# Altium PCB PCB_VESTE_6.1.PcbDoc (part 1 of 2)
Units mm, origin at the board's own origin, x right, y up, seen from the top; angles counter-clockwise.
Board outline 60.48 x 91 mm, 4 copper layers (Top Copper (GND), Signal Layer 1 (PWR), Signal Layer 2 (GND), Bottom Copper(SIG)), stack 0.97 mm thick; 103 components, 68 nets, 385 pads, 720 vias.
Unrouted connection lines stored in the file: 5.
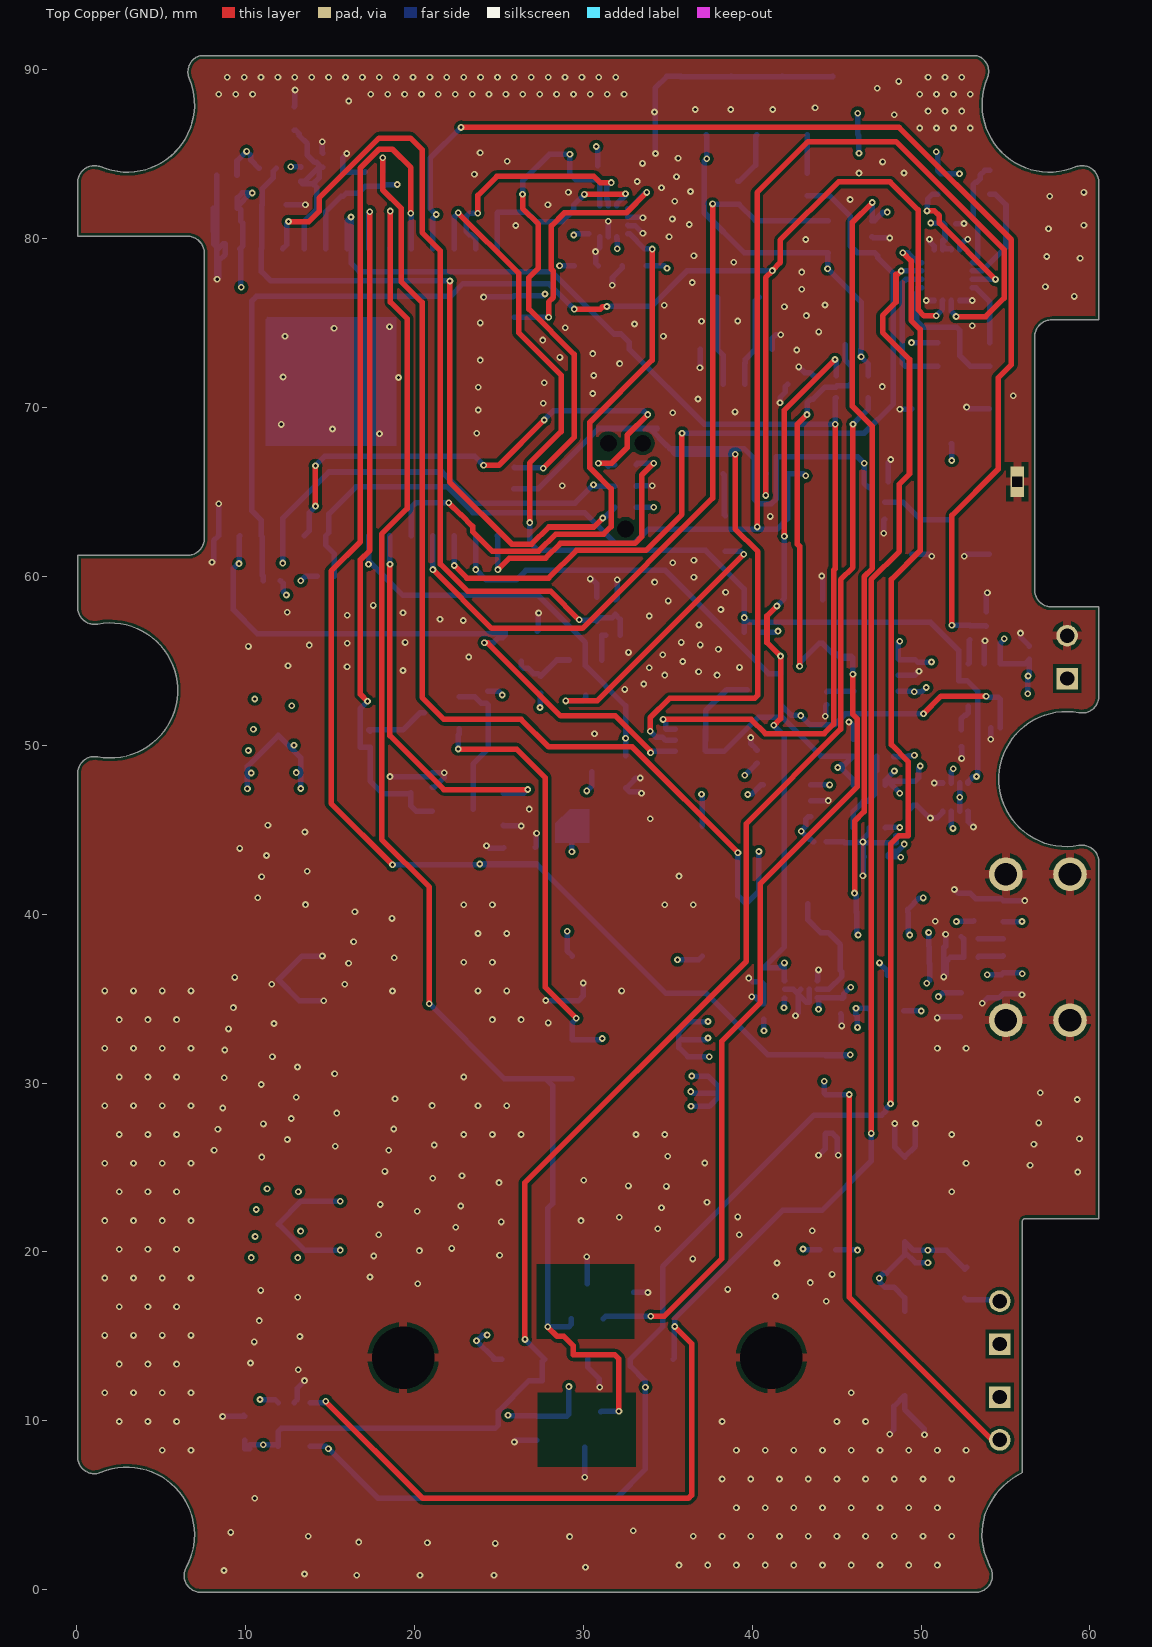
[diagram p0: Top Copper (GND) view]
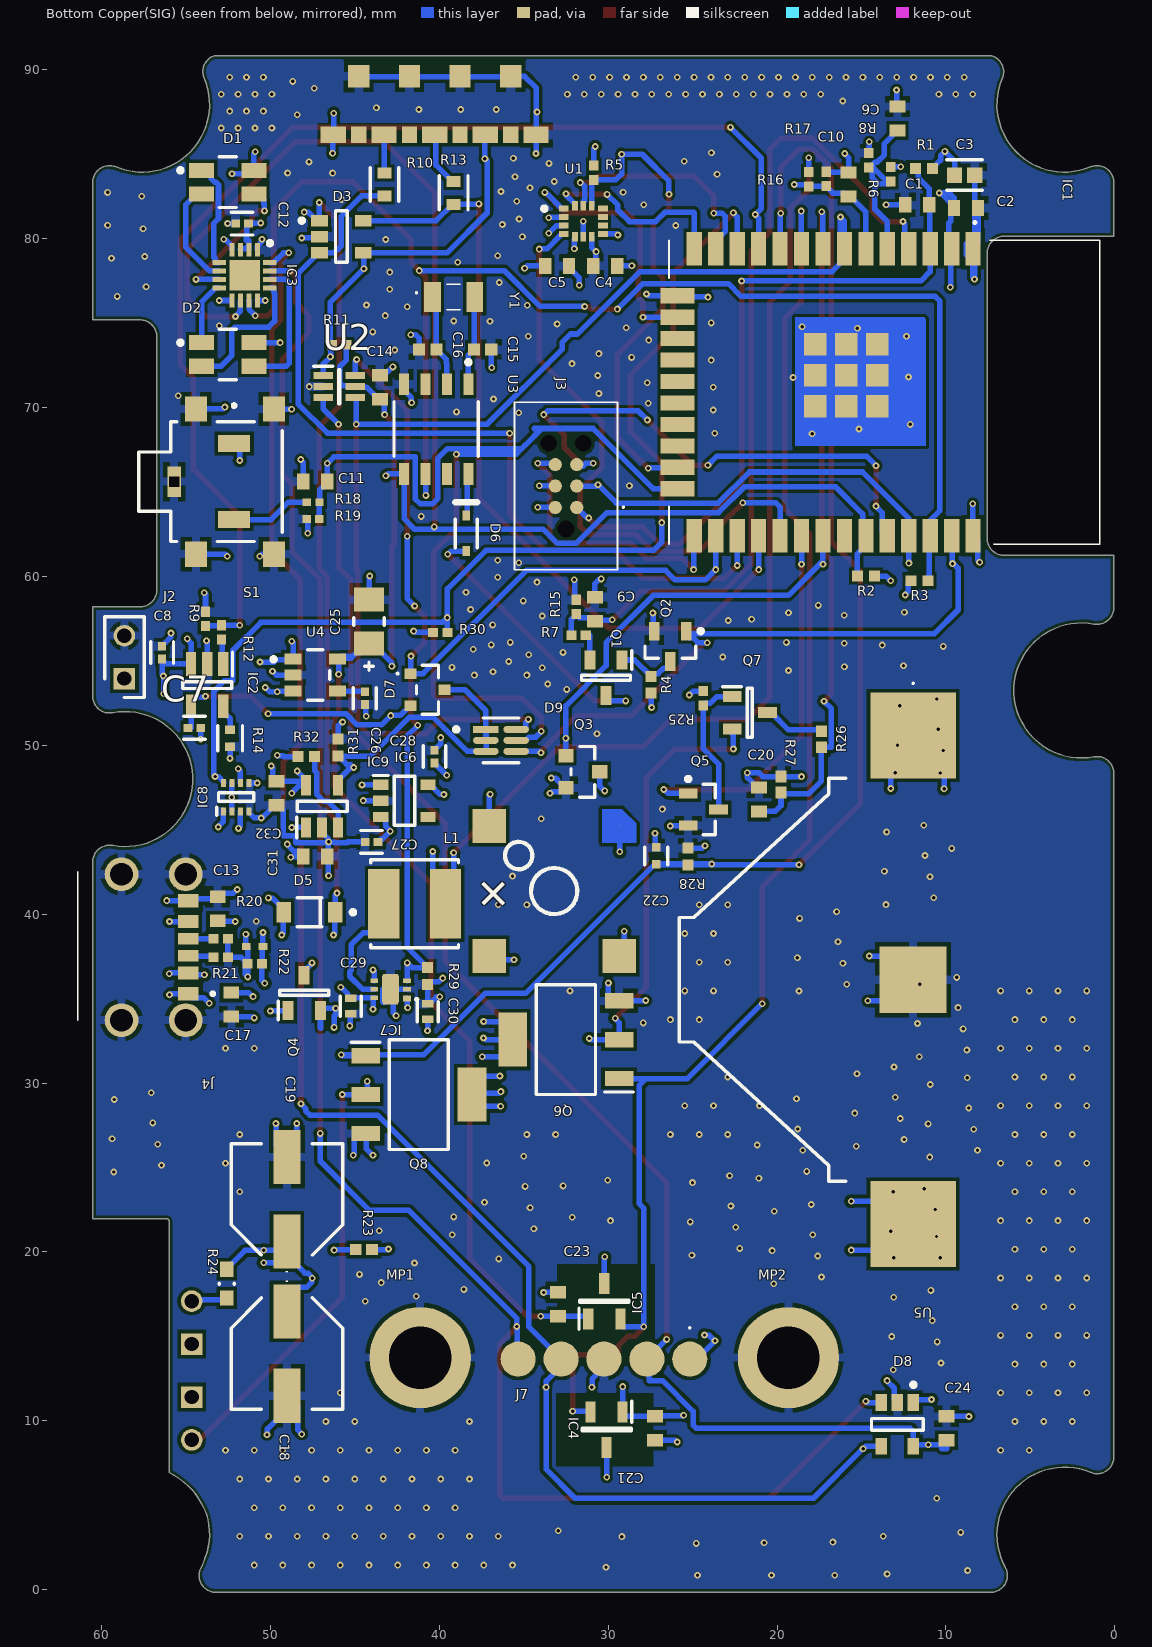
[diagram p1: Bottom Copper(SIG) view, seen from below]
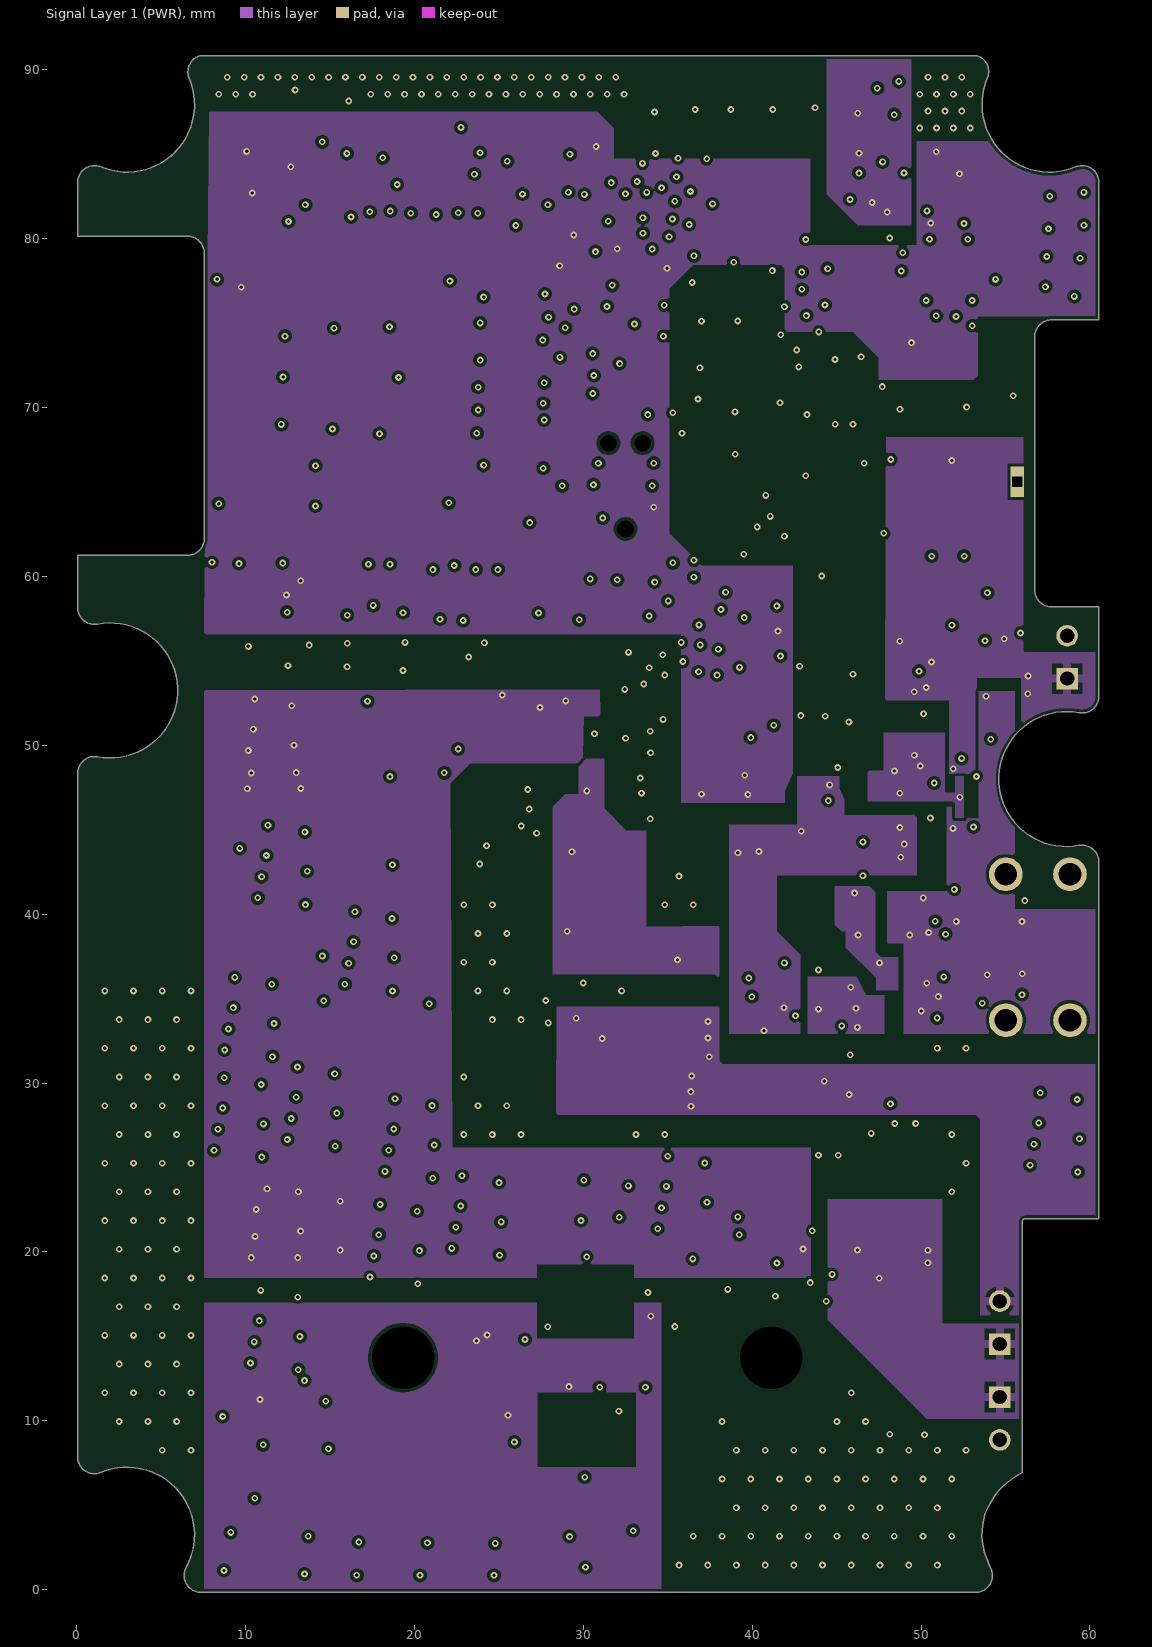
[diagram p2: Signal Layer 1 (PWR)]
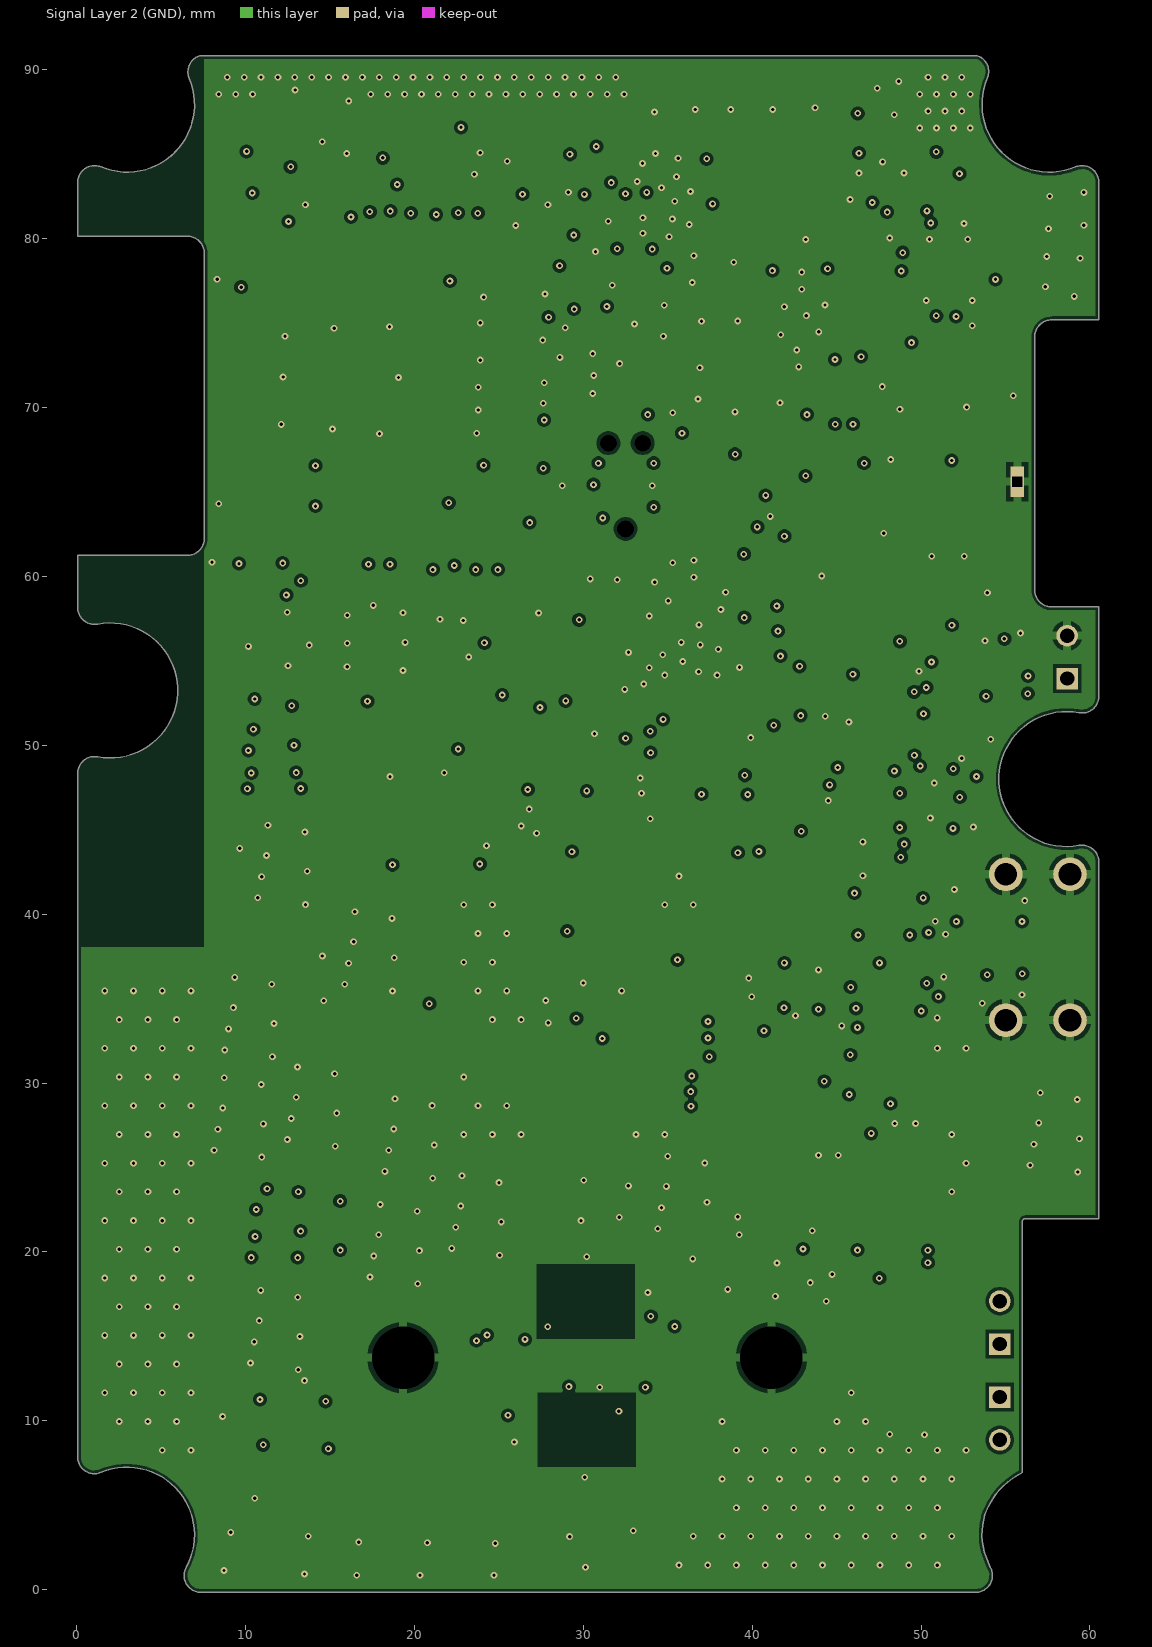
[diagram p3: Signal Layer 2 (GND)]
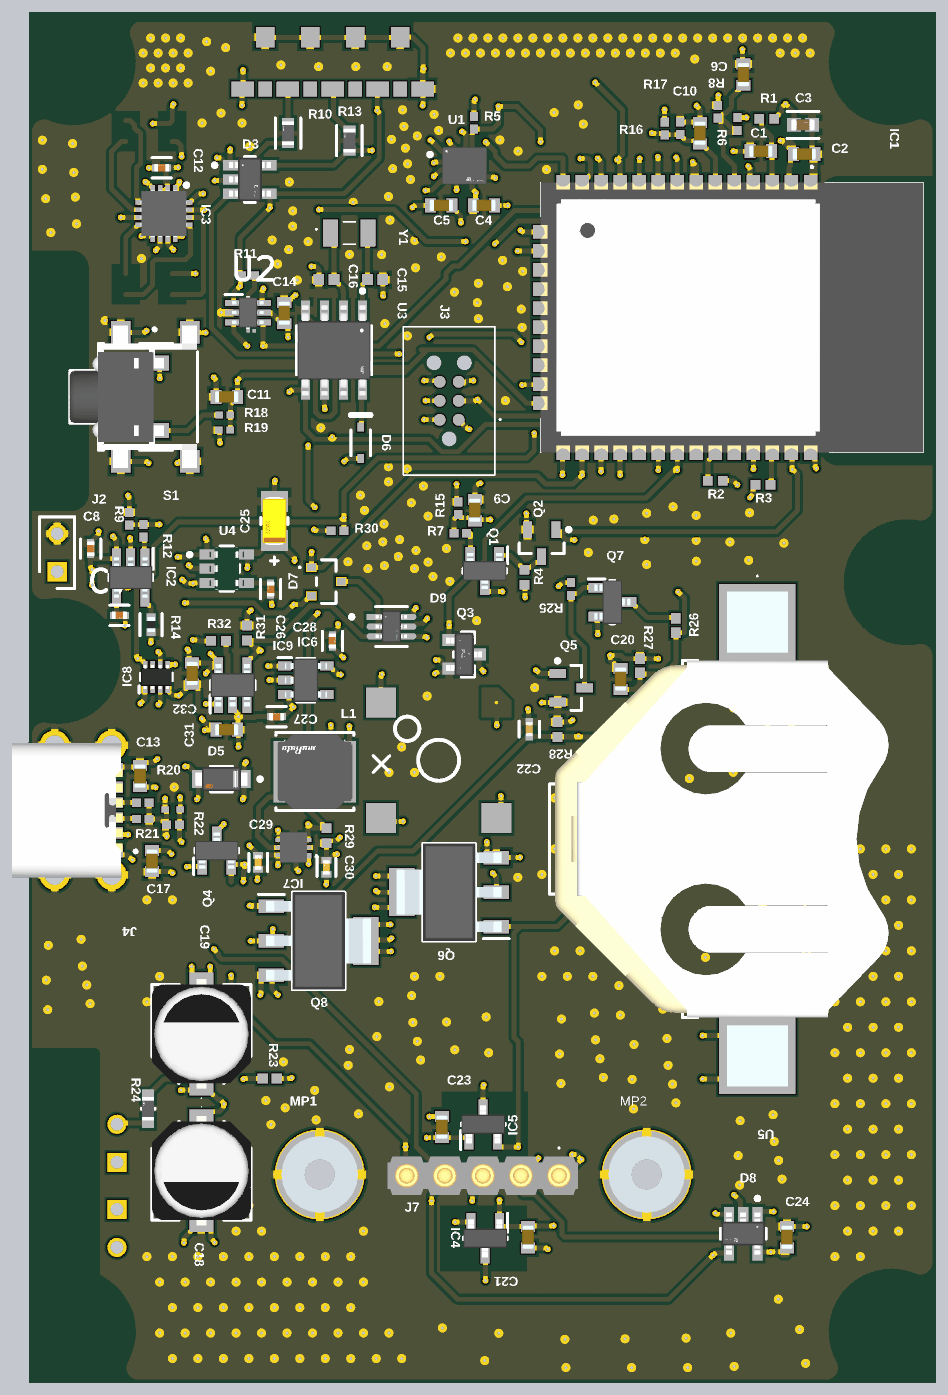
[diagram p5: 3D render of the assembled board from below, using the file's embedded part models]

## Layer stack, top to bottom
Top Mask: solder mask 0.015, Solder Resist, Dk 3.8
Top Copper (GND): signal copper 0.035
Dielectric 1: prepreg 0.2, 7628, Dk 4.6
Signal Layer 1 (PWR): signal copper 0.0175
Core: core 0.465, FR-4, Dk 4.5
Signal Layer 2 (GND): signal copper 0.0175
Dielectric 2: prepreg 0.2, 7628, Dk 4.6
Bottom Copper(SIG): signal copper 0.035
Bottom Mask: solder mask 0.015, Solder Resist, Dk 3.8

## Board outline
0.053,7.862 ccw(c1.053,7.862) 1.438,6.939 cw(c2.977,3.247) 6.482,1.319 ccw(c7.358,0.837) 7.358,-0.162 53.225,-0.162 ccw(c53.225,0.838) 54.102,1.319 cw(c58.745,3.625) 53.616,2.872 cw(c58.647,3.184) 53.767,4.447 cw(c58.841,2.431) 54.642,5.92 cw(c58.524,2.168) 55.996,6.939 55.993,9.925 55.993,14.87 cw(c55.995,14.866) 55.996,14.87 55.996,21.804 cw(c56.16,21.804) 56.159,21.968 60.53,21.968 60.53,43.083 ccw(c59.531,43.083) 59.346,44.066 cw(c58.607,47.997) 59.346,51.928 ccw(c59.53,52.911) 60.53,52.911 60.53,58.192 57.73,58.192 cw(c57.73,59.192) 56.73,59.192 56.73,74.192 cw(c57.73,74.192) 57.73,75.192 60.53,75.192 60.53,83.322 ccw(c59.531,83.322) 59.146,84.245 cw(c57.607,87.937) 53.923,89.496 ccw(c53.002,89.885) 53.308,90.838 7.3,90.838 ccw(c7.584,89.879) 6.663,89.49 cw(c2.977,87.936) 1.438,84.245 ccw(c1.053,83.322) 0.053,83.322 0.053,80.142 6.553,80.142 cw(c6.553,79.142) 7.553,79.142 7.553,62.242 cw(c6.554,62.241) 6.553,61.242 0.053,61.242 0.053,58.161 ccw(c1.053,58.161) 1.238,57.178 cw(c1.977,53.247) 1.238,49.316 ccw(c1.053,48.333) 0.053,48.333

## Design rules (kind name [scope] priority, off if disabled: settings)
BoardOutlineClearance [All] p1: gap=0.2 ignorepadtopadclearanceinfootprint=FALSE except(0.4: Arc-SplitBarrior Arc-SplitContinuation Track-SplitBarrior Track-SplitContinuation SMDPad-SplitBarrior SMDPad-SplitContinuation THPad-SplitBarrior THPad-SplitContinuation Via-SplitBarrior Via-SplitContinuation Fill-SplitBarrior Fill-SplitContinuation Poly-SplitBarrior Poly-SplitContinuation Region-SplitBarrior Region-SplitContinuation Text-SplitBarrior Text-SplitContinuation)
Clearance "Clearance Bottom Layer" [OnLayer('Bottom Layer')] p1: gap=0.203 ignorepadtopadclearanceinfootprint=TRUE except(0.254: Arc-Text Track-Text SMDPad-Text THPad-Text Via-Text Fill-Text Poly-Text Region-Text Text-Text)
Clearance "Clearance Top Layer" [OnLayer('Top Layer')] p2: gap=0.203 ignorepadtopadclearanceinfootprint=TRUE except(0.254: Arc-Text Track-Text SMDPad-Text THPad-Text Via-Text Fill-Text Poly-Text Region-Text Text-Text)
Clearance [All] p3: gap=0.2 ignorepadtopadclearanceinfootprint=FALSE except(0.089: Arc-Arc Arc-Track Arc-SMDPad Track-Track Track-SMDPad SMDPad-SMDPad; 0.127: Arc-Via Track-Via SMDPad-Via THPad-Via Via-Via; 0.254: Arc-Text Track-Text SMDPad-Text THPad-Text Via-Text Fill-Text Poly-Text Region-Text Text-Text)
HoleSize [All] p1: absolutevalues=TRUE maxlimit=6.3 minlimit=0.2 maxpercent=80.000 minpercent=20.000
MinimumAnnularRing [All] p1: minimumring=0.076
MinimumSolderMaskSliver [All] p1: minsoldermaskwidth=0.1
PolygonConnect PolygonConnect_1 [All] p1: thpad.connectstyle=Relief thpad.reliefconductorwidth=0.508 thpad.reliefentries=4 thpad.polygonreliefangle="90 Angle" thpad.airgapwidth=0.254 smdpad.connectstyle=Relief smdpad.reliefconductorwidth=0.508 smdpad.reliefentries=4 smdpad.polygonreliefangle="90 Angle" smdpad.airgapwidth=0.254 via.connectstyle=Direct via.reliefconductorwidth=0.508 via.reliefentries=4 via.polygonreliefangle="90 Angle" via.airgapwidth=0.254
RoomDefinition VESTE_V3.1_MCU [InComponentClass('VESTE_V3.1_MCU')] p1: confinementstyle=ConfineIn formatcopy=TRUE lockcomponents=FALSE outline -189.586,-112.446 -138.786,-112.446 -138.786,-87.046 -189.586,-87.046
RoutingCorners [All] p1: cornerstyle=Round minsetback=2.54 maxsetback=2.54
RoutingVias [All] p1: holewidth=0.2 width=0.4 viastyle="Through Hole" minholewidth=0.15 minwidth=0.3 maxholewidth=1 maxwidth=2
SilkToSilkClearance [All] p1: silktosilkclearance=0.1
SilkToSolderMaskClearance [IsPad] p1: minsilkscreentomaskgap=0.1 clearancetoexposedcopper=TRUE
SolderMaskExpansion [All] p1: expansion=0.102 istentingtop=FALSE
Width [All] p1: maxlimit=0.326 minlimit=0.217 preferedwidth=0.326 toplayer_minwidth=0.326 midlayer1_maxwidth=0.217 midlayer1_prefwidth=0.217 midlayer2_maxwidth=0.217 midlayer2_prefwidth=0.217 bottomlayer_minwidth=0.326 impedanceprofiledriven=TRUE impedanceprofileid={350D186C-2408-4C7B-B652-4617568C561D} impedanceprofilevalue=50.000000 minimp=50.000000 maximp=50.000000 favimp=50.000000
25 further rules are at their usual default settings.

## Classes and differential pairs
component class VESTE_V3.1_PSU: C7 C8 C13 C17 C18 C19 C25 C26 C27 C28 C29 C30 C31 C32 D5 D7 D9 IC2 IC6 IC7 IC8 IC9 J2 J4 L1 MP1 MP2 Q4 R9 R12 R14 R20 R21 R22 R23 R24 R29 R30 R31 R32 U4 U5
component class VESTE_V3.1_MCU: C1 C2 C3 C4 C5 C6 C9 C10 C11 C12 C14 C15 C16 C20 C21 C22 C23 C24 D1 D2 D3 D6 D8 IC1 IC3 IC4 IC5 J3 J7 Q1 Q2 Q3 Q5 Q6 Q7 Q8 R1 R2 R3 R4 R5 R6 R7 R8 R10 R11 R13 R15 R16 R17 R18 R19 R25 R26 R27 R28 S1 U1 U2 U3 Y1

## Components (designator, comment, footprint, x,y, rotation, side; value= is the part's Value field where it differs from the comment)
C1 "" CAPC1608X90N 11.705,82.004 r0 bottom
C2 "" CAPC1608X90N 8.808,81.813 r180 bottom
C3 "GRM188R61A226ME15D" FP-GRM188-0_2-IPC_C 8.89,83.762 r180 bottom
C4 "" CAPC1608X90N 30.18,78.39 r0 bottom
C5 "" CAPC1608X90N 33.025,78.39 r180 bottom
C6 "" CAPC1608X90N 12.867,87.115 r90 bottom
C7 "CL05A475KP5NRNC" FP-CL828-IPC_C 54.5,51.036 r180 bottom
C8 "CL05A475KP5NRNC" FP-CL828-IPC_C 56.417,55.486 r90 bottom
C9 "" CAPC1608X90N 30.787,58.056 r90 bottom
C10 "" CAPC1608X90N 15.765,83.209 r90 bottom
C11 "" CAPC1608X90N 47.34,65.614 r0 bottom
C12 "CL05A105KP5NNNC" FP-CL511-IPC_C 51.679,80.894 r0 bottom
C13 "" CAPC1608X90N 53.123,40.313 r90 bottom
C14 "" CAPC1608X90N 43.502,71.201 r90 bottom
C15 "CC0402JRNPO9BN100" CAPC1005X55X25ML05T05 37.435,73.44 r0 bottom
C16 "CC0402JRNPO9BN100" CAPC1005X55X25ML05T05 40.685,73.44 r180 bottom
C17 "" CAPC1608X90N 52.317,34.645 r270 bottom
C18 "EEEFT1A221AP" EEE1AA101SP 49.029,13.982 r270 bottom
C19 "EEEFT1A221AP" EEE1AA101SP 49.029,23.114 r90 bottom
C20 "" CAPC1608X90N 21.06,46.79 r90 bottom
C21 "" CAPC1608X90N 27.231,9.549 r270 bottom
C22 "CC0402KRX7R9BB103" FP-CC0402-MFG 27.154,43.449 r90 bottom value=10nF
C23 "" CAPC1608X90N 32.977,16.897 r90 bottom
C24 "" CAPC1608X90N 9.959,9.549 r90 bottom
C25 "TAJA225K016RNJ" FP-TAJA-MFG 44.162,57.33 r270 bottom
C26 "CL05B471KB5NNNC" FP-CL23-IPC_C 44.412,52.788 r270 bottom
C27 "CL05A105KP5NNNC" FP-CL511-IPC_C 44.014,44.277 r0 bottom
C28 "CL05A105KP5NNNC" FP-CL511-IPC_C 40.284,49.327 r90 bottom
C29 "CL05A106MP5NUNC" FP-CL05A106MP5NUNC-MFG 45.242,34.555 r270 bottom value=10uF
C30 "CL05A106MP5NUNC" FP-CL05A106MP5NUNC-MFG 40.687,34.227 r90 bottom value=10uF
C31 "" CAPC1608X90N 47.339,43.41 r0 bottom
C32 "" CAPC1608X90N 49.644,47.161 r270 bottom
D1 "150141M173100" WL-SFTW_3528_150141M173100 -1217.473,1353.343 r180 bottom locked
D2 "150141M173100" WL-SFTW_3528_150141M173100 -1217.473,1343.143 r180 bottom locked
D3 "SP0504BAHTG" FP-SP0504BAHTG-MFG 45.797,80.119 r180 bottom value=30pF
D5 "RB168MM100TR" FP-PMDU-MFG 47.692,40.113 r0 bottom
D6 "1N4148WS-7-F" DIOD-SOD323-2-A_V 38.404,62.547 r90 bottom
D7 "BAT54C" NXP-SOT23-3_V 40.698,53.288 r90 bottom
D8 "SP0504BAHTG" FP-SP0504BAHTG-MFG 12.879,9.784 r270 bottom value=30pF
D9 "SD103ATW-7-F" FP-SOT363-IPC_A 36.348,50.286 r180 bottom
IC1 "ESP32-WROOM-32__16MB_" ESP32WROOM3216MB 13.65,70.904 r270 bottom locked
IC2 "MCP73831-2ACI_OT" SOT95P270X145-5N 53.743,53.563 r270 bottom
IC3 "SC620ULTRT" QFN50P300X300X60-17N 51.527,77.837 r270 bottom
IC4 "TMAG5231A1CQDBZR" SOT95P237X112-3N 30.094,9.474 r270 bottom
IC5 "TMAG5231A1CQDBZR" SOT95P237X112-3N 30.231,17.076 r90 bottom
IC6 "XC6210B332MR-G" SOT95P280X130-5N 42.062,46.711 r180 bottom
IC7 "XC9142A50CER-G" XC9142A50CERG 42.887,35.555 r0 bottom
IC8 "TPS2116DRLR" SOTFL50P160X60-8N 52.027,46.927 r90 bottom
IC9 "AP2171WG-7" SOT95P282X130-5N 46.939,46.377 r90 bottom
J2 "3-644456-2" HDRV2W67P0X254_1X2_478X234X1029P 58.649,53.95 r270 bottom
J3 "TC2030-MCP-NL-10" TC2030MCPNL10 32.298,65.351 r90 bottom
J4 "TYPE-C-31-M-17" TYPEC31M17 57.367,38.04 r270 bottom locked
J7 "811-22-005-30-022101" 8112200530022101 30.25,13.65 r0 bottom
L1 "LQH5BPN4R7NT0L" FP-LQH5BPB_T0-MFG 41.462,40.613 r0 bottom
MP1 "9774035151R" 9774035151 41.135,13.735 r180 bottom
MP2 "9774035151R" 9774035151 19.325,13.735 r180 bottom
Q1 "DMP3125L-7" SOT96P240X110-3N 30.128,53.999 r270 bottom
Q2 "2N7002P,215" NXP-SOT23_L 26.323,55.862 r270 bottom
Q3 "DMN3730U-7" FP-SOT23-MFG 31.503,48.428 r180 bottom
Q4 "DMP3125L-7" SOT96P240X110-3N 48.006,35.343 r90 bottom
Q5 "2N7002P,215" NXP-SOT23_L 24.367,46.202 r180 bottom
Q6 "NDT3055L" SOT230P700X180-4N 32.503,32.566 r0 bottom
Q7 "DMP3125L-7" SOT96P240X110-3N 21.615,51.926 r180 bottom
Q8 "NDT3055L" SOT230P700X180-4N 41.211,29.316 r180 bottom
R1 "ERJ-2GEJ103X" RESC1005X40X25ML05T05 11.303,84.162 r180 bottom
R2 "ERJ-2GEJ103X" RESC1005X40X25ML05T05 14.74,60.018 r0 bottom
R3 "ERJ-2GEJ103X" RESC1005X40X25ML05T05 11.557,59.743 r180 bottom
R4 "ERJ-2GEJ103X" RESC1005X40X25ML05T05 27.47,53.586 r90 bottom
R5 "RC0402FR-07100KL" RESC1005X40X25NL05T10 30.848,83.902 r90 bottom
R6 "RC0402FR-07100KL" RESC1005X40X25NL05T10 13.267,83.812 r90 bottom
R7 "RC0402FR-07100KL" RESC1005X40X25NL05T10 31.751,56.514 r180 bottom
R8 "RC0402FR-07100KL" RESC1005X40X25NL05T10 14.576,84.643 r270 bottom
R9 "RC0402FR-079K1L" RESC1005X40X25NL05T10 53.845,57.48 r90 bottom
R10 "RC0603FR-071KL" FP-RC0603-0_55-IPC_C 43.249,83.209 r90 bottom
R11 "RC0402FR-07100KL" RESC1005X40X25NL05T10 45.923,73.715 r0 bottom
R12 "RC0402FR-074K7L" RESC1005X40X25NL05T10 52.895,56.683 r270 bottom
R13 "RC0603FR-071KL" FP-RC0603-0_55-IPC_C 39.154,82.709 r90 bottom
R14 "RC0402FR-072KL" FP-RC_L0402-MFG 52.39,50.411 r270 bottom value=2kΩ
R15 "RC0402FR-07100KL" RESC1005X40X25NL05T10 31.89,58.189 r270 bottom
R16 "RC0402FR-07100KL" RESC1005X40X25NL05T10 18.122,83.523 r90 bottom
R17 "RC0402FR-07100KL" RESC1005X40X25NL05T10 17.08,83.537 r270 bottom
R18 "RC0402FR-0730KL" RESC1005X40X25LL05T10 47.469,64.397 r180 bottom
R19 "RC0402FR-07110KL" RESC1005X40X25LL05T10 47.484,63.397 r180 bottom
R20 "RC0402FR-075K1L" RESC1005X40X25NL05T10 52.945,38.54 r0 bottom
R21 "RC0402FR-075K1L" RESC1005X40X25NL05T10 52.945,37.452 r0 bottom
R22 "RC0402FR-07100KL" RESC1005X40X25NL05T10 50.928,37.069 r180 bottom
R23 "RC0402FR-0756KL" RESC1005X40X25ML05T10 44.47,20.139 r180 bottom
R24 "RC0603FR-0747KL" FP-RC0603FR-0747KL-MFG 52.582,18.119 r90 bottom
R25 "RC0402FR-07100KL" RESC1005X40X25NL05T10 24.367,52.788 r90 bottom
R26 "RC0402FR-0756KL" RESC1005X40X25ML05T10 17.377,50.354 r270 bottom
R27 "RC0402FR-0768KL" RESC1005X40X25ML05T10 19.766,47.669 r90 bottom
R28 "ERJ-2GEJ103X" RESC1005X40X25ML05T05 25.277,43.423 r270 bottom
R29 "ERJ-2GEJ103X" RESC1005X40X25ML05T05 40.687,36.337 r270 bottom
R30 "RC0402FR-07100KL" RESC1005X40X25NL05T10 39.945,56.683 r180 bottom
R31 "ERJ-2GEJ103X" RESC1005X40X25ML05T05 45.989,49.861 r90 bottom
R32 "ERJ-2GEJ103X" RESC1005X40X25ML05T05 47.881,49.336 r0 bottom
S1 "TL3336AF160Q" TL3336AF160Q 52.6,65.614 r90 bottom
U1 "LSM6DS3TR" FP-LGA-14-DM00249496-MFG 31.475,81.031 r180 bottom
U2 "SN74AUP2G04DCKR" SOT65P210X110-6N 45.923,71.24 r180 bottom
U3 "PCF8563T/5,518" FP-SOT96-1-MFG 40.185,68.727 r270 bottom
U4 "MIC5205-3.3YM5-TR" FP-M5-MFG 47.34,54.156 r180 bottom
U5 "3024-2" 30242 11.941,36.116 r270 bottom
Y1 "Q13FC1350000400" Q13FC1350000400 39.154,76.542 r180 bottom

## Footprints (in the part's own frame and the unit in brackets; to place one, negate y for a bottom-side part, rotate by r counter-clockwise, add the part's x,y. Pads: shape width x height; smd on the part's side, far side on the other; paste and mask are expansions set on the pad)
30242 [mm]
  rect 5.08x5.08 smd: 1(-14.465,0) 2(14.465,0)
  rect 3.96x3.96 smd: 3(0,0)
  silkscreen extent -17.6,-13.85 11.93,0.05, body extent -17.01,-13.49 17.01,8.76, height 0.1
9774035151 [mm] "SMT Steel Spacer with internal Thread M2.5, height 3.5mm"
  round 6 / inner round 0 / far side round 0 hole 3.7 unplated: 1(0,0)
  body extent -2.55,-2.55 2.55,2.55, height 3.5
8112200530022101 [mm]
  round 2.08 smd: 1(-5.08,0) 2(-2.54,0) 3(0,0) 4(2.54,0) 5(5.08,0)
  silkscreen extent -5.13,-1.9 -5.03,-1.8, body extent -6.35,-1.27 6.35,1.27, height 3.49
CAPC1005X55X25ML05T05 [mm] "Chip Capacitor, 2-Leads, Body 1.00x0.50mm, IPC Low Density"
  rect 0.72x0.72 smd: 1(-0.51,0) 2(0.51,0)
  body extent -0.53,-0.28 0.53,0.27, height 0.55
CAPC1608X90N [mm]
  rect 0.73x0.94 smd: 1(-0.71,0) 2(0.71,0)
  body extent -0.8,-0.4 0.8,0.4, height 0.9
DIOD-SOD323-2-A_V [mm] "SOD-323, 2-Leads, Body 1.7x1.3mm"
  rect 0.59x0.45 smd: 1(-1.055,0) 2(1.055,0)
  silkscreen extent -0.85,-0.65 1.85,0.65, body extent -0.85,-0.65 0.85,0.65, height 1.2
EEE1AA101SP [mm]
  rect 3.2x1.6 smd: 1(-2.5,0) 2(2.5,0)
  silkscreen extent -4.88,-3.3 3.3,3.3, body extent -3.65,-3.3 3.65,3.3, height 5.8
ESP32WROOM3216MB [mm]
  rect 2x0.9 smd: 1(-8.5,5.26) 2(-8.5,3.99) 3(-8.5,2.72) 4(-8.5,1.45) 5(-8.5,0.18) 6(-8.5,-1.09) 7(-8.5,-2.36) 8(-8.5,-3.63) 9(-8.5,-4.9) 10(-8.5,-6.17) 11(-8.5,-7.44) 12(-8.5,-8.71) 13(-8.5,-9.98) 14(-8.5,-11.25) 25(8.5,-11.25) 26(8.5,-9.98) 27(8.5,-8.71) 28(8.5,-7.44) 29(8.5,-6.17) 30(8.5,-4.9) 31(8.5,-3.63) 32(8.5,-2.36) 33(8.5,-1.09) 34(8.5,0.18) 35(8.5,1.45) 36(8.5,2.72) 37(8.5,3.99) 38(8.5,5.26)
  rect 0.9x2 smd: 15(-5.715,-12.25) 16(-4.445,-12.25) 17(-3.175,-12.25) 18(-1.905,-12.25) 19(-0.635,-12.25) 20(0.635,-12.25) 21(1.905,-12.25) 22(3.175,-12.25) 23(4.445,-12.25) 24(5.715,-12.25)
  rect 1.33x1.33 smd: 39(-2.835,-0.405) 40(-1,-0.405) 41(0.835,-0.405) 42(-2.835,-2.24) 43(-1,-2.24) 44(0.835,-2.24) 45(-2.835,-4.075) 46(-1,-4.075) 47(0.835,-4.075)
  silkscreen extent -10.1,-12.75 9,12.75, body extent -9,-12.75 9,12.75, height 3.1
FP-CC0402-MFG [mm]
  rect 0.5x0.5 smd paste+0 mask+0: 1(-0.5,0) 2(0.5,0)
  silkscreen extent -0.53,-0.68 0.52,0.67, body extent -0.5,-0.25 0.5,0.25, height 0.55
FP-CL05A106MP5NUNC-MFG [mm]
  rect 0.45x0.675 smd paste+0 mask+0: 1(-0.463,0) 2(0.462,0)
  silkscreen extent -0.6,-0.63 0.6,0.63, body extent -0.5,-0.25 0.5,0.25, height 0.7
FP-CL23-IPC_C [mm]
  rect 0.515x0.472 smd paste+0 mask+0: 1(-0.379,0) 2(0.379,0)
  silkscreen extent -0.64,-0.67 0.64,0.68, body extent -0.5,-0.25 0.5,0.25, height 0.55
FP-CL511-IPC_C [mm]
  rect 0.515x0.472 smd paste+0 mask+0: 1(-0.379,0) 2(0.379,0)
  silkscreen extent -0.64,-0.68 0.64,0.67, body extent -0.5,-0.25 0.5,0.25, height 0.55
FP-CL828-IPC_C [mm]
  rect 0.515x0.472 smd paste+0 mask+0: 1(-0.379,0) 2(0.379,0)
  silkscreen extent -0.64,-0.67 0.64,0.67, body extent -0.5,-0.25 0.5,0.25, height 0.55
FP-GRM188-0_2-IPC_C [mm]
  rect 0.905x0.906 smd paste+0 mask+0: 1(-0.601,0) 2(0.601,0)
  silkscreen extent -1.05,-0.9 1.05,0.9, body extent -0.8,-0.4 0.8,0.4, height 1
FP-LGA-14-DM00249496-MFG [mm]
  rect 0.575x0.35 smd paste+0 mask+0: 1(-1.162,0.75) 2(-1.162,0.25) 3(-1.162,-0.25) 4(-1.162,-0.75) 8(1.163,-0.75) 9(1.163,-0.25) 10(1.163,0.25) 11(1.163,0.75)
  rect 0.35x0.575 smd paste+0 mask+0: 5(-0.5,-0.912) 6(0,-0.912) 7(0.5,-0.912) 12(0.5,0.913) 13(0,0.913) 14(-0.5,0.913)
  silkscreen extent -2.43,0.63 -2.18,0.87, body extent -1.5,-1.25 1.5,1.25, height 0.86
FP-LQH5BPB_T0-MFG [mm]
  rect 1.85x4.1 smd paste+0 mask+0: 1(-1.825,0) 2(1.825,0)
  silkscreen extent -2.6,-2.6 2.6,2.6, body extent -2.5,-2.5 2.5,2.5, height 2.2
FP-M5-MFG [mm]
  rect 1x0.66 smd paste+0 mask+0: 1(-1.315,0.95) 2(-1.315,0) 3(-1.315,-0.95) 4(1.315,-0.95) 5(1.315,0.95)
  silkscreen extent -2.6,-1.5 0.85,1.5, body extent -1.4,-1.46 1.4,1.46, height 1.3
FP-PMDU-MFG [mm]
  rect 0.85x1.2 smd paste+0 mask+0: 1(-1.525,0) 2(1.525,0)
  silkscreen extent -2.7,-0.85 0.73,0.85, body extent -1.75,-0.8 1.75,0.8, height 0.9
FP-RC0603-0_55-IPC_C [mm]
  rect 0.659x0.812 smd paste+0 mask+0: 1(-0.677,0) 2(0.677,0)
  silkscreen extent -1.01,-0.85 1.01,0.85, body extent -0.8,-0.4 0.8,0.4, height 0.55
FP-RC0603FR-0747KL-MFG [mm]
  rect 0.9x0.8 smd paste+0 mask+0: 1(-0.85,0) 2(0.85,0)
  silkscreen extent -0.02,-0.45 0.02,0.45, body extent -0.8,-0.4 0.8,0.4, height 0.55
FP-RC_L0402-MFG [mm]
  rect 0.5x0.6 smd paste+0 mask+0: 1(-0.5,0) 2(0.5,0)
  silkscreen extent -0.74,-0.74 0.74,0.74, body extent -0.5,-0.25 0.5,0.25, height 0.4
FP-SOT23-MFG [mm]
  rect 0.9x0.8 smd paste+0 mask+0: 1(-1,0.95) 2(-1,-0.95) 3(1,0)
  silkscreen extent -0.7,-1.5 0.7,1.5, body extent -1.2,-1.45 1.2,1.45, height 1.1
FP-SOT96-1-MFG [mm]
  rect 1.3x0.6 smd paste+0 mask+0: 1(-2.65,1.905) 2(-2.65,0.635) 3(-2.65,-0.635) 4(-2.65,-1.905) 5(2.65,-1.905) 6(2.65,-0.635) 7(2.65,0.635) 8(2.65,1.905)
  silkscreen extent -4.07,-2.5 1.62,2.5, body extent -2.99,-2.45 3.01,2.45, height 1.75
FP-SOT363-IPC_A [mm]
  rect 1.51x0.412 smd paste+0 mask+0: 1(-0.901,0.65)
  rrect100% 1.51x0.412 smd paste+0 mask+0: 2(-0.901,0) 3(-0.901,-0.65) 4(0.901,-0.65) 5(0.901,0) 6(0.901,0.65)
  silkscreen extent -2.78,-1.32 1.05,1.32, body extent -1.05,-1.07 1.05,1.07, height 1.1
FP-SP0504BAHTG-MFG [mm]
  rect 0.99x0.69 smd paste+0 mask+0: 1(-1.295,0.95) 2(-1.295,0) 3(-1.295,-0.95) 4(1.295,-0.95) 5(1.295,0.95)
  silkscreen extent -2.48,-1.52 0.35,1.53, body extent -1.4,-1.45 1.4,1.45, height 1.45
FP-TAJA-MFG [mm]
  rect 1.4x1.8 smd paste+0 mask+0: 1(-1.3,0) 2(1.3,0)
  silkscreen extent -0.23,-0.9 2.9,0.9, body extent -1.6,-0.8 1.6,0.8, height 1.8
HDRV2W67P0X254_1X2_478X234X1029P [mm]
  rect 1.275x1.275 hole 0.85: 1(0,0)
  round 1.275 hole 0.85: 2(-2.54,0)
  silkscreen extent -3.66,-1.17 1.12,1.17
NXP-SOT23-3_V [mm] "SOT23, 3-Leads, Body 1.3x2.9mm, Pitch 0.95mm"
  rect 0.6x0.7 smd paste-0.05: 1(0.95,1) 2(-0.95,1) 3(0,-1)
  silkscreen extent -1.45,-0.65 1.45,1.79, body extent -1.45,-0.65 1.45,0.65, height 1.1
NXP-SOT23_L [mm] "SOT23, 3-Leads, Body 3x1.4mm, Pitch 0.95mm, IPC High Density"
  rect 1.1x0.6 smd: 1(-0.9,0.95) 2(-0.9,-0.95) 3(0.9,0)
  silkscreen extent -1.02,-1.5 0.7,1.92, body extent -0.7,-1.5 0.7,1.5, height 1.1
Q13FC1350000400 [mm]
  rect 1x1.8 smd: 1(-1.25,0) 2(1.25,0)
  silkscreen extent -2.25,-0.75 0.4,0.75
QFN50P300X300X60-17N [mm]
  rect 0.8x0.3 smd: 1(-1.5,0.75) 2(-1.5,0.25) 3(-1.5,-0.25) 4(-1.5,-0.75) 9(1.5,-0.75) 10(1.5,-0.25) 11(1.5,0.25) 12(1.5,0.75)
  rect 0.3x0.8 smd: 5(-0.75,-1.5) 6(-0.25,-1.5) 7(0.25,-1.5) 8(0.75,-1.5) 13(0.75,1.5) 14(0.25,1.5) 15(-0.25,1.5) 16(-0.75,1.5)
  rect 1.8x1.8 smd: 17(0,0)
  silkscreen extent -2.02,1.37 -1.78,1.62, body extent -1.55,-1.55 1.55,1.55, height 0.6
RESC1005X40X25LL05T10 [mm] "Chip Resistor, 2-Leads, Body 1.00x0.50mm, IPC High Density"
  rect 0.5x0.45 smd: 1(-0.375,0) 2(0.375,0)
  body extent -0.53,-0.27 0.53,0.28, height 0.4
RESC1005X40X25ML05T05 [mm] "Chip Resistor, 2-Leads, Body 1.00x0.50mm, IPC Low Density"
  rect 0.65x0.65 smd: 1(-0.5,0) 2(0.5,0)
  body extent -0.53,-0.27 0.53,0.28, height 0.4
RESC1005X40X25ML05T10 [mm] "Chip Resistor, 2-Leads, Body 1.00x0.50mm, IPC Low Density"
  rect 0.7x0.65 smd: 1(-0.475,0) 2(0.475,0)
  body extent -0.53,-0.27 0.53,0.28, height 0.4
RESC1005X40X25NL05T10 [mm] "Chip Resistor, 2-Leads, Body 1.00x0.50mm, IPC Medium Density"
  rect 0.6x0.55 smd: 1(-0.425,0) 2(0.425,0)
  body extent -0.53,-0.27 0.53,0.28, height 0.4
SOT65P210X110-6N [mm]
  rect 1.15x0.4 smd: 1(-0.95,0.65) 2(-0.95,0) 3(-0.95,-0.65) 4(0.95,-0.65) 5(0.95,0) 6(0.95,0.65)
  silkscreen extent -1.53,-1.01 0.03,1.2, body extent -1.05,-1.01 1.05,1.01, height 1.1
SOT95P237X112-3N [mm]
  rect 1.25x0.6 smd: 1(-1.05,0.95) 2(-1.05,-0.95) 3(1.05,0)
  silkscreen extent -1.67,-1.46 0.08,1.5, body extent -1.27,-1.46 1.27,1.46, height 1
SOT95P270X145-5N [mm]
  rect 1.4x0.6 smd: 1(-1.25,0.95) 2(-1.25,0) 3(-1.25,-0.95) 4(1.25,-0.95) 5(1.25,0.95)
  silkscreen extent -1.95,-1.45 0.2,1.5, body extent -1.35,-1.45 1.35,1.45, height 1.45
SOT95P280X130-5N [mm]
  rect 0.9x0.6 smd: 1(-1.4,0.95) 2(-1.4,0) 3(-1.4,-0.95) 4(1.4,-0.95) 5(1.4,0.95)
  silkscreen extent -1.85,-1.45 0.6,1.5, body extent -1.4,-1.45 1.4,1.45, height 1.3
SOT95P282X130-5N [mm]
  rect 1.2x0.6 smd: 1(-1.25,0.95) 2(-1.25,0) 3(-1.25,-0.95) 4(1.25,-0.95) 5(1.25,0.95)
  silkscreen extent -1.85,-1.48 0.3,1.5, body extent -1.41,-1.48 1.41,1.48, height 1.3
SOT96P240X110-3N [mm]
  rect 1.1x0.65 smd: 1(-1.05,0.96) 2(-1.05,-0.96) 3(1.05,0)
  silkscreen extent -1.6,-1.45 0.15,1.54, body extent -1.2,-1.45 1.2,1.45, height 1.1
SOT230P700X180-4N [mm]
  rect 1.7x0.9 smd: 1(-3.15,2.3) 2(-3.15,0) 3(-3.15,-2.3)
  rect 1.7x3.2 smd: 4(3.15,0)
  silkscreen extent -4,-3.25 1.75,3.25, body extent -3.5,-3.25 3.5,3.25, height 1.8
SOTFL50P160X60-8N [mm]
  rect 0.475x0.3 smd: 1(-0.838,0.75) 2(-0.838,0.25) 3(-0.838,-0.25) 4(-0.838,-0.75) 5(0.838,-0.75) 6(0.838,-0.25) 7(0.838,0.25) 8(0.838,0.75)
  silkscreen extent -1.07,-1.05 0.25,1.15, body extent -0.8,-1.05 0.8,1.05, height 0.6
TC2030MCPNL10 [mil]
  round 30.98 smd: 1(-50,-17.09) 2(-50,32.91) 3(0,-17.09) 4(0,32.91) 5(50,-17.09) 6(50,32.91)
  round 19.49 hole 39.02 unplated: 7(-100,7.91) 8(100,47.91) 9(100,-32.09)
  silkscreen extent -195,-128 195,128
TL3336AF160Q [mm]
  rect 1x1.9 smd: 1(2.25,-0.45) 2(-2.25,-0.45)
  rect 1.5x1.3 smd: MP1(4.3,1.8) MP2(4.3,-2.8) MP3(-4.3,-2.8) MP4(-4.3,1.8)
  rect 1.8x0.8 hole 0.6 square: MP5(0,3.1)
  silkscreen extent -3.55,-3.3 4.6,5.2, body extent -4.75,-3.28 4.75,5.22, height 7.11
TYPEC31M17 [mm]
  rect 0.7x1.2 smd: A5(-0.5,2.5) B5(0.5,2.5)
  rect 0.76x1.2 smd: A9(1.52,2.5) B9(-1.52,2.5)
  rect 0.8x1.2 smd: A12(2.75,2.5) B12(-2.75,2.5)
  round 2 hole 1.346: MH1(-4.32,-1.45) MH2(4.32,-1.45) MH3(4.32,2.35) MH4(-4.32,2.35)
  silkscreen extent -4.47,-4.05 4.32,4.05, body extent -4.47,-4.31 4.48,3.09, height 3.26
WL-SFTW_3528_150141M173100 [mm] "SMT Full-color TOP LED Waterclear, body 3.5x2.8mm"
  rect 1.5x0.9 smd: 1(-1268.45,-1269.3) 2(-1268.45,-1270.7) 3(-1271.55,-1269.3) 4(-1271.55,-1270.7)
  silkscreen extent -1272.93,-1271.5 -1269.5,-1268.5, body extent -1271.75,-1271.4 -1268.25,-1268.6, height 1.9
XC9142A50CERG [mm]
  rect 0.45x0.35 smd: 1(-0.975,0.55)
  rect 0.45x0.25 smd: 2(-0.975,0) 3(-0.975,-0.5) 4(0.975,-0.5) 5(0.975,0) 6(0.975,0.5)
  rect 0.9x1.8 smd: 7(0,0)
  rect 0.05x1.6 smd: 8(-0.475,0) 9(0.475,0)
  silkscreen extent -1.6,0.55 -1.5,0.65, body extent -0.9,-1 0.9,1, height 0.7

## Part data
C1 C2 C4 C5 C6 C9 C10 C11 C13 C14 C17 C20 C21 C23 C24 C31: library part CL10B104KB8NNNC, "Capacitor", Capacitance=100nF, Manufacturer_Name=SAMSUNG, Mouser Part Number=187-CL10B104KB8NNNC
C3: library part CMP-2000-06337-3, "Chip Multilayer Ceramic Capacitors for General Purpose, 0603, 22uF, X5R, 15%, 20%, 10V", Capacitance=22uF, Case Code (Imperial)=0603, Case Code (Metric)=1608, Dielectric=X5R, Max Operating Temperature=85°C, Min Operating Temperature=-55°C, Package Quantity=4000, Tolerance=20%, Voltage Rating=10V
C7 C8: library part CMP-13271-001251-1, "Cap Ceramic 4.7uF 10V X5R ±10% SMD 0402 +85°C Paper T/R", Capacitance=4.7uF, Case Code (Imperial)=0402, Case Code (Metric)=1005, Dielectric=X5R, Max Operating Temperature=85°C, Min Operating Temperature=-55°C, Package Quantity=1, Tolerance=10%, Voltage Rating=10V
C12 C27 C28: library part CMP-13271-001936-1, "Cap Ceramic 1uF 10V X5R ±10% SMD 0402 +85°C Paper T/R", Capacitance=1uF, Case Code (Imperial)=0402, Case Code (Metric)=1005, Dielectric=X5R, Max Operating Temperature=85°C, Min Operating Temperature=-55°C, Package Quantity=1, Tolerance=10%, Voltage Rating=10V
C15 C16: library part CMP-2100-03589-1, "Chip Capacitor, 10 pF, +/- 5%, 50 V, -55 to 125 degC, 0402 (1005 Metric), RoHS, Tape and Reel", Capacitance=10pF, Case Code (Imperial)=0402, Case Code (Metric)=1005, Dielectric=C0G, Dielectric Material=Ceramic, Insulation Resistance=100GR, Manufacturer=Yageo, Max Operating Temperature=125degC, Min Operating Temperature=-55degC, Package Description="2-Pin Surface Mount Device, Body 1 x 0.5 mm", Package Quantity=1, Temperature Coefficient=30ppm/degC, Tolerance=5%, Voltage=50V
C18 C19: "Capacitor Polarised", Manufacturer_Name=Panasonic
C22: library part CMP-2100-03592-2, "CAP CER 10000PF 50V X7R 0402", Capacitance=10nF, Manufacturer=YAGEO, Package=CC0402, Temperature="-55°C to +125°C", Temperature Characteristic=X7R, Temperature Coefficient=30ppm/°C, Temperature Range High=+125°C, Temperature Range Low=-55°C, Tolerance=0.1, Voltage Rating="50 V"
C25: library part CMP-04424-000432-1, "2.2uF 16V  ±10% 6.5Ω 1206  SMD Tantalum Capacitor", Capacitance=2.2uF, Case Code (Imperial)=1206, Case Code (Metric)=3216, Dielectric Material=Tantalum, ESR (Equivalent Series Resistance)=6.5R, Leakage Current=500nA, Max Operating Temperature=125°C, Min Operating Temperature=-55°C, Package Quantity=1, Tolerance=10%, Voltage=16V
C26: library part CMP-13271-000495-1, "Cap Ceramic 470pF 50V X7R ±10% SMD 0402 +125°C Paper T/R", Capacitance=470pF, Case Code (Imperial)=0402, Case Code (Metric)=1005, Dielectric=X7R, Max Operating Temperature=125°C, Min Operating Temperature=-55°C, Package Quantity=1, Tolerance=10%, Voltage=50V
C29 C30: library part CMP-13271-000002-1, "CAP CER 10UF 10V X5R 0402", Capacitance=10uF, Manufacturer=Samsung, Temperature="-55°C to +85°C", Temperature Characteristic=X5R, Temperature Coefficient=15%, Temperature Range High=+85°C, Temperature Range Low=-55°C, Tolerance=20%, Voltage Rating=10V
C32: library part CL10B104KB8NNNC, "Capacitor", Capacitance=100n, Manufacturer_Name=SAMSUNG, Mouser Part Number=187-CL10B104KB8NNNC
D1 D2: library part CMP-1431-00001-2, Case Code (Imperial)=1411, Case Code (Metric)=3528, Color="Green, Red", Forward Current=100mA, Forward Voltage=3.2V, Max Operating Temperature=85°C, Max Reverse Voltage (DC)=5V, Min Operating Temperature=-40°C, Power Dissipation=72mW, Test Current=20mA
D3 D8: library part CMP-08607-000010-1, "TVS DIODE 5.5V 8.5V SOT23-5", Capacitance=30pF, Clamping Voltage=8.5V, Manufacturer=Littelfuse, Reverse Standoff Voltage=5.5V, Temperature="-40°C to +125°C", Temperature Range High=+125°C, Temperature Range Low=-40°C
D5: library part CMP-08971-000001-1, "DIODE SCHOTTKY 100V 1A SOD123FL", Forward Current=1A, Manufacturer="ROHM Semiconductor", Max Junction Temp=+150°C, Max Repetitive Reverse Voltage=100V, Max Surge Forward Current=40A, Package=PMDU, Peak Reverse Current=0.4uA, Temperature="to +150°C"
D6: library part CMP-1667-00004-1, "Fast Switching Diode, 75 V, 0.3 A, -65 to 150 degC, 2-Pin SOD323, RoHS, Tape and Reel"
D7: library part CMP-0417-00003-1, "Schottky Barrier Diode, 30 V, 2 uA, -55 to 150 degC, 3-Pin SOT23, RoHS, Tape and Reel", Manufacturer="NXP Semiconductors", Temperature Range="-55 to 150 degC"
D9: library part CMP-12790-000076-1, "DIODE ARRAY SCHOTTKY 40V SOT363", Average Rectified Current=175mA, Capacitance=50pF, Case/Package=SOT-363, Current Rating=350mA, Forward Voltage=500mV, Max Forward Surge Current (Ifsm)=1A, Max Operating Temperature=125°C, Max Power Dissipation=200mW, Max Repetitive Reverse Voltage (Vrrm)=40V, Min Operating Temperature=-55°C, Package Quantity=3000, Peak Reverse Current=5uA
IC1: "Integrated Circuit", Manufacturer_Name="Espressif Systems", Manufacturer_Part_Number="ESP32-WROOM-32 (16MB)", Mouser Part Number=356-ESPWROOM3216MB
IC2: "Integrated Circuit", Manufacturer_Name=Microchip, Manufacturer_Part_Number=MCP73831-2ACI/OT
IC3: "Integrated Circuit", Manufacturer_Name=SEMTECH, Mouser Part Number=947-SC620ULTRT
IC4 IC5: "Integrated Circuit", Manufacturer_Name="Texas Instruments", Mouser Part Number=595-TMAG5231A1CQDBZR
IC6: "Integrated Circuit", Manufacturer_Name=Torex, Mouser Part Number=865-XC6210B332MR-G
IC7: "Integrated Circuit", Manufacturer_Name=Torex, Mouser Part Number=865-XC9142A50CER-G
IC8: "Integrated Circuit", Manufacturer_Name="Texas Instruments", Mouser Part Number=595-TPS2116DRLR
IC9: "Integrated Circuit", Manufacturer_Name="Diodes Inc.", Mouser Part Number=621-AP2171WG-7
J2: "Connector", Manufacturer_Name="TE Connectivity", Mouser Part Number=571-3-644456-2
J3: "Connector", Manufacturer_Name="Tag Connect"
J4: "Connector", Manufacturer_Name="Korean Hroparts Elec"
J7: "Connector 5 pin Height  5,512 mm", Manufacturer_Name=Mill-Max, Mouser Part Number=575-8112200530022101
L1: library part CMP-06042-004027-1, "Wire Wound Ferrite Inductor for Power Lines 4.7μH ±30% 0.0696Ω 2.0A 2020", Case Code (Imperial)=2020, Case Code (Metric)=5050, Case/Package=Nonstandard, Current Rating=2A, DC Resistance (DCR)=58mR, Inductance=4.7uH, Inductance Tolerance=30%, Max DC Current=3A, Max Operating Temperature=125°C, Min Operating Temperature=-40°C, Package Quantity=500, Resistor Type=Wirewound, Self Resonant Frequency=40MHz, Test Frequency=100kHz
MP1 MP2: library part CMP-03913-118307956-1, "9774035151R WA-SMSI SMT Steel Spacer, M2.5 Internal non Stop", Max Operating Temperature=150°C, Min Operating Temperature=-55°C
Q1 Q4 Q7: "MOSFET (P-Channel)", Manufacturer_Name="Diodes Inc.", Mouser Part Number=621-DMP3125L-7
Q2 Q5: library part CMP-1259-00082-1, "N-Channel Trench MOSFET, 60 V, 0.36 A, -55 to 150 degC, 3-Pin SOT23, Tape and Reel", Manufacturer="NXP Semiconductors"
Q3: library part CMP-12801-000041-1, "MOSFET N-CH 30V 750MA SOT23", Continuous Drain Current=0.75A, Drain To Source Breakdown Voltage=30V, Drain To Source Resistance=460mΩ, Gate To Source Voltage=8V, Input Capacitace At Vds="64.3pF @ 25V", Manufacturer="Diodes Inc.", Max Forward Diode Voltage=1.2V, Max Junction Temp=+150°C, Package=SOT23, Power Dissipation=0.45W, Pulse Drain Current=10A, Temperature="-55°C to +150°C", Temperature Range Low=-55°C, Typ Forward Diode Voltage=0.7V
Q6 Q8: "Transistor", Manufacturer_Name=onsemi, Mouser Part Number=512-NDT3055L
R1 R2 R3 R4 R28 R29 R31 R32: library part CMP-2002-00433-1, Manufacturer=Panasonic, Resistance=10K
R5 R6 R7 R8 R11 R15 R16 R17 R22 R25 R30: library part CMP-2002-07343-1, Manufacturer="Yageo / Phycomp", Resistance=100K
R9: library part CMP-2002-07017-1, Manufacturer="Yageo / Phycomp", Resistance=9.1K
R10 R13: library part CMP-1659-00009-5, "RES 1K OHM 1% 1/10W 0603", Case Code (Imperial)=0603, Case Code (Metric)=1608, Max Operating Temperature=155°C, Max Power Dissipation=100mW, Min Operating Temperature=-55°C, Resistance=1kR, Resistance Tolerance=1%, Resistor Type="Thick Film", Temperature Coefficient=100ppm/°C, Voltage Rating=50V
R12: library part CMP-1011-00586-2, Manufacturer="Yageo / Phycomp", Resistance=4.7K
R14: library part CMP-2002-07580-2, "RES SMD 2K OHM 1% 1/16W 0402", Manufacturer=Yageo, Package=RC_L0402, Power Rating=0.0625W, Resistance=2kΩ, Temperature="-55°C to +155°C", Temperature Coefficient=100ppm/°C, Temperature Range High=+155°C, Temperature Range Low=-55°C, Tolerance=1%, Voltage Rating=50V
R18: library part CMP-2002-07602-1, Manufacturer="Yageo / Phycomp", Resistance=30K
R19: library part CMP-2002-07022-1, Manufacturer="Yageo / Phycomp", Resistance=110K
R20 R21: library part CMP-2002-07753-1, Manufacturer="Yageo / Phycomp", Resistance=5K1
R23 R26: library part CMP-1011-00708-2, Manufacturer="Yageo / Phycomp", Resistance=56K
R24: library part CMP-1659-00055-2, "RES SMD 47K OHM 1% 1/10W 0603", Case Code (Imperial)=0603, Case Code (Metric)=1608, Max Operating Temperature=155°C, Max Power Dissipation=100mW, Min Operating Temperature=-55°C, Package Quantity=1, Resistance=47kR, Resistance Tolerance=1%, Resistor Type="Thick Film", Temperature Coefficient=100ppm/°C, Voltage Rating=50V
R27: library part CMP-1011-00717-2, Manufacturer="Yageo / Phycomp", Resistance=68K
S1: "Switch", Manufacturer_Name=E-Switch, Mouser Part Number=612-TL3336AF160Q
U1: library part CMP-2000-05193-2, "IMU ACCEL/GYRO I2C/SPI 14VFLGA", Manufacturer=STMicroelectronics, Max Supply Voltage=3.6V, Min Supply Voltage=1.62V, Operating Supply Current=9-900uA, Package=LGA-14-DM00249496, Temperature="-40°C to +85°C", Temperature Range High=+85°C, Temperature Range Low=-40°C
U2: "Integrated Circuit", Manufacturer_Name="Texas Instruments", Mouser Part Number=595-SN74AUP2G04DCKR
U3: library part CMP-10083-000010-1, "IC RTC CLK/CALENDAR I2C 8-SOIC", Ambient Temperature Range High=+85°C, Ambient Temperature Range Low=-40°C, Frequency=400kHz, Manufacturer=NXP, Max Supply Voltage=5.5V, Min Supply Voltage=1V, Nominal Supply Current=0.225-0.95uA, Package=SOT96-1, Temperature="-40°C to +85°C"
U4: library part CMP-06324-000014-1, "IC REG LINEAR 3.3V 150MA SOT23-5", Dropout Voltage=165mV, Manufacturer=Microchip, Max Junction Temp=+125°C, Max Supply Voltage=16V, Min Supply Voltage=2.5V, Output Current=150mA, Package=M5, Temperature="-40°C to +125°C", Temperature Range Low=-40°C
U5: "Undefined or Miscellaneous", Manufacturer_Name="Keystone Electronics", Mouser Part Number=534-3024-2
Y1: "Crystal or Oscillator", Manufacturer_Name="Seiko Epson Corporation"

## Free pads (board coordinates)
  rect 1.5x1 smd far side: 1(46.271,86.151) 3(43.271,86.151) 5(40.271,86.151) 7(37.271,86.151) 9(34.271,86.151)
  rect 0.51x0.42 smd far side: 1(50.444,38.09) 2(51.444,38.09)
  rect 1.275x1.275 hole 0.85: 1(54.661,11.405) 1(54.662,14.542)
  rect 0.9x1 smd far side: 2(44.771,86.151) 4(41.771,86.151) 6(38.771,86.151) 8(35.771,86.151)
  round 1.275 hole 0.85: 2(54.661,8.865) 2(54.662,17.082)
  rect 2x2 smd far side paste+0 mask+0.051: 3(29.349,37.519) +(37.049,45.219) -(37.049,37.519)
  round 0.025 smd far side: 4(29.349,45.219)
  rect 1.25x1.35 smd far side: 10(44.771,89.611) 11(41.771,89.611) 12(38.771,89.611) 13(35.771,89.611)

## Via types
v1: diameter 0.4, hole 0.2, Top Copper (GND) to Bottom Copper(SIG), 720 vias

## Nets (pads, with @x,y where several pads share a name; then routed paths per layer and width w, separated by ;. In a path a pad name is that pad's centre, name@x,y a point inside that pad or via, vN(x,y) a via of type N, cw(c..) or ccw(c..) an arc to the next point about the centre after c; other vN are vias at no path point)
3V3: C2.1 C3.1 C4.1 C5.1 C12.1 C28.1 D1.1 D2.1 IC1.2 IC3.2 IC3.3 IC6.5 J3.2 pad.+ R1.2 R2.1 R3.1 R5.2 R6.2 R30.1 U1.5 U1.8 | length 32
  Bottom Copper(SIG) w0.326: C3.1@9.491,83.762 9.491,84.599 v1(10.06,85.168) 10.316,84.911 10.316,84.648 R1.2@10.803,84.162 ; C2.1@9.518,81.813 C2.1@9.518,81.918 ; v1(9.74,77.124) 9.725,77.139 9.725,79.339 IC1.2@9.66,79.404 9.82,79.564 9.82,80.879 9.834,80.893 9.834,80.913 9.72,81.028 9.72,81.716 C2.1@9.518,81.918 ; R3.1@12.057,59.743 12.219,59.581 12.219,59.112 12.415,58.916 v1(12.415,58.896) ; v1(12.671,84.254) 12.679,84.245 13.259,84.245 R6.2@13.267,84.237 ; v1(13.27,59.743) 13.548,60.021 14.237,60.021 R2.1@14.24,60.018 ; v1(28.593,78.39) C4.1@29.47,78.39 ; v1(29.425,80.219) 29.445,80.219 29.507,80.281 U1.8@30.313,80.281 ; v1(30.769,85.457) 30.769,85.437 30.848,85.358 R5.2@30.848,84.327 ; U1.5@31.975,80.119 31.987,80.107 31.987,79.971 32.002,79.956 v1(32.002,79.408) ; J3.2@33.134,64.081 33.141,64.089 34.157,64.089 v1(34.165,64.097) ; C5.1@33.735,78.39 34.793,78.39 34.93,78.252 v1(34.95,78.252) ; v1(36.994,47.101) 36.994,47.081 37.049,47.026 pad.+@37.049,45.219 ; v1(39.562,48.224) 39.582,48.224 40.211,48.854 40.211,48.875 C28.1@40.284,48.948 ; v1(39.728,47.082) 39.743,47.096 39.947,47.096 40.512,47.661 IC6.5@40.662,47.661 ; R30.1@40.37,56.683 41.424,56.683 41.503,56.762 v1(41.523,56.762) ; v1(49.429,73.843) D2.1@50.977,73.843 ; v1(50.575,80.926) 50.589,80.912 51.282,80.912 C12.1@51.3,80.894 51.322,80.894 51.395,80.821 51.395,80.8 51.396,80.798 51.396,80.233 51.424,80.205 51.424,79.914 51.277,79.914 IC3.2@51.277,79.587 ; v1(50.898,85.143) 50.898,85.123 50.977,85.043 D1.1@50.977,84.043 51.163,83.857 52.263,83.857 v1(52.277,83.843) ; IC3.2@51.277,79.337 IC3.2@51.277,79.587 ; IC3.3@51.777,79.337 51.777,79.383 51.764,79.396 51.469,79.396 51.402,79.462 IC3.2@51.277,79.587 ; C2.1@9.518,81.918 10.291,82.691 10.385,82.691 v1(10.399,82.705) 9.804,82.705 9.518,82.419 C2.1@9.518,81.918
3V3_LC: C14.1 C21.1 C23.1 C25.2 D8.1 IC4.1 IC5.1 J7.1 R11.1 U2.5 U4.5 | length 83.1
  Top Copper (GND) w0.326: v1(33.997,16.187) 34.781,16.187 38.202,19.607 38.202,32.487 40.488,34.773 40.488,41.807 46.216,47.535 46.216,51.579 45.962,51.833 v1(45.962,54.201) ; v1(42.807,54.674) 42.807,61.776 42.672,61.91 42.672,69.012 v1(43.242,69.582)
  Bottom Copper(SIG) w0.326: v1(10.854,11.256) 11.752,11.256 D8.1@11.929,11.079 ; v1(24.3,15.075) 24.286,15.061 24.016,15.061 23.693,14.739 v1(23.673,14.739) 23.673,14.727 24.695,13.705 24.695,13.65 J7.1@25.17,13.65 ; v1(25.536,10.319) 25.55,10.305 27.186,10.305 C21.1@27.231,10.259 29.007,10.259 29.144,10.396 IC4.1@29.144,10.524 v1(29.144,12.024) ; IC5.1@31.181,16.026 31.181,16.05 31.318,16.187 C23.1@32.977,16.187 v1(33.997,16.187) ; v1(42.807,54.674) 42.821,54.688 42.821,54.888 43.962,56.03 C25.2@44.162,56.03 44.699,55.493 44.899,55.493 45.227,55.165 U4.5@45.967,55.165 ; v1(43.242,69.582) 43.256,69.596 43.256,70.289 C14.1@43.404,70.437 ; C14.1@43.502,70.491 43.607,70.491 44.319,71.203 44.936,71.203 45.01,71.277 45.707,71.277 45.898,71.468 45.898,72.414 45.498,72.814 R11.1@45.498,73.715 ; 45.119,55.273 45.858,55.273 45.962,55.169 v1(45.962,54.201)
5V: C29.1 IC7.6 Q4.2 | length 7.2
  Bottom Copper(SIG) w0.326: IC7.6@43.862,35.055 43.926,35.055 43.926,34.891 ; v1(43.926,34.363) 43.926,34.891 ; v1(45.833,35.676) 45.417,35.26 45.417,35.08 45.355,35.018 C29.1@45.242,35.018 45.223,35.036 43.905,35.036 43.924,35.017 43.924,34.893 43.926,34.891 ; v1(46.143,34.423) 46.143,34.052 46.217,33.978 46.217,33.306 v1(46.231,33.292) ; v1(46.143,34.423) 46.884,34.423 47.03,34.277 Q4.2@47.03,34.231 ; Q4.2@47.03,34.03 47.03,33.25 47.046,33.266 47.046,34.03 Q4.2@47.046,34.293
5V_SELLE: D3.1 D5.1 pad.1@46.271,86.151 Q4.3 | length 50.4
  Top Copper (GND) w0.326: v1(46.059,41.246) 46.059,45.5 46.631,46.072 46.631,59.98 47.119,60.468 47.119,68.882 45.923,70.079 45.923,80.958 v1(47.109,82.144)
  Bottom Copper(SIG) w0.326: v1(46.059,41.246) 46.059,41.226 46.167,41.118 D5.1@46.167,40.113 46.178,40.102 46.178,38.873 46.268,38.783 v1(46.268,38.763) ; v1(46.249,87.419) 46.249,86.173 pad.1@46.271,86.151 46.32,86.102 v1(46.32,85.063) ; v1(47.109,82.144) 47.109,81.086 D3.1@47.092,81.069 47.242,81.069 47.73,81.558 47.98,81.558 v1(47.994,81.572) ; v1(47.536,37.113) 47.55,37.099 47.55,37.073 48.006,36.618 Q4.3@48.006,36.393
ALIM_ON: D7.3 D9.1 D9.2 D9.3 IC9.4 R31.1 | length 19.3
  Bottom Copper(SIG) w0.326: D9.2@37.249,50.286 D9.1@37.249,50.936 ; D7.3@39.698,53.288 38.492,53.288 37.249,52.045 D9.1@37.249,50.936 ; IC9.4@45.989,47.627 45.989,47.927 45.248,48.668 45.077,48.668 v1(45.062,48.682) 45.082,48.682 45.252,48.852 45.479,48.852 R31.1@45.989,49.361 44.068,49.361 41.759,51.671 40.368,51.671 38.333,49.636 D9.3@37.249,49.636 37.221,49.665 37.221,50.908 D9.1@37.249,50.936
ALIM_ONOFF: D9.4 IC1.37 Q2.1 | length 37
  Top Copper (GND) w0.326: v1(24.14,56.064) 24.327,56.064 28.651,51.74 31.902,51.74 33.982,49.66 v1(33.982,49.562)
  Bottom Copper(SIG) w0.326: IC1.37@9.66,62.404 9.622,62.366 9.622,60.772 v1(9.608,60.757) 9.55,60.757 9.271,60.478 9.271,58.024 10.678,56.617 Q2.1@25.373,56.617 ; v1(24.14,56.064) 24.155,56.078 24.69,56.078 24.986,56.375 25.236,56.375 25.373,56.512 Q2.1@25.373,56.762 ; v1(33.982,49.562) 34.002,49.562 34.076,49.636 D9.4@35.447,49.636
ALUM_PYRO: pad.2@54.661,8.865 pad.2@54.662,17.082 Q6.2 Q6.4 Q7.2 Q8.2 Q8.4 R24.1 | length 66.7
  Top Copper (GND) w0.326: v1(22.586,49.776) 26.043,49.776 27.737,48.082 27.737,35.679 v1(29.584,33.832) ; v1(45.742,29.316) 45.742,17.317 54.194,8.865 pad.2@54.661,8.865
  Bottom Copper(SIG) w0.326: v1(22.586,49.776) 22.586,50.598 22.665,50.678 Q7.2@22.665,50.966 ; v1(29.584,33.832) 29.584,33.812 29.353,33.58 Q6.2@29.353,32.566 31.035,32.566 31.104,32.635 v1(31.124,32.635) ; v1(36.353,29.492) 36.373,29.492 36.478,29.387 37.991,29.387 37.991,29.797 37.375,30.413 v1(36.414,30.413) ; v1(36.373,28.623) 37.454,28.623 38.061,29.23 Q8.4@38.061,29.316 ; v1(37.379,33.64) 36.26,33.64 35.653,33.033 Q6.4@35.653,32.566 ; v1(37.38,32.663) 37.36,32.663 37.263,32.566 Q6.4@35.653,32.566 ; v1(37.46,31.558) 36.187,31.558 35.653,32.092 Q6.4@35.653,32.566 ; v1(44.266,30.103) 44.266,29.412 Q8.2@44.361,29.316 v1(45.742,29.316) ; R24.1@52.582,17.269 52.675,17.176 54.569,17.176 pad.2@54.662,17.082
BAT_LVL: C10.1 IC1.6 R16.1 R17.2 | length 7.1
  Bottom Copper(SIG) w0.326: IC1.6@14.74,79.404 14.74,81.579 15.66,82.499 C10.1@15.765,82.499 15.967,82.701 16.694,82.701 17.08,83.087 R17.2@17.08,83.112 17.087,83.105 18.116,83.105 R16.1@18.122,83.098 18.219,83.195 18.962,83.195 v1(18.976,83.209)
BP: C11.1 D9.5 IC1.24 R18.2 R19.2 | length 60.5
  Top Copper (GND) w0.326: v1(33.961,50.829) 33.961,51.638 35.104,52.781 40.144,52.781 40.335,52.972 40.335,61.468 38.989,62.814 v1(38.989,67.234)
  Bottom Copper(SIG) w0.326: IC1.24@25.888,65.202 IC1.24@25.9,65.189 27.318,65.189 27.343,65.214 30.886,68.758 33.934,68.758 ; v1(33.961,50.829) 33.961,50.809 34.29,50.48 34.682,50.48 34.875,50.286 D9.5@35.447,50.286 ; 34.366,68.758 33.934,68.758 ; v1(38.989,67.234) 35.458,67.234 35.128,67.564 ; C11.1@46.63,65.615 v1(46.629,66.7) 46.248,67.081 41.427,67.081 41.427,64.592 41.123,64.287 40.411,64.287 40.107,64.592 40.107,66.98 39.522,67.564 35.128,67.564 ; C11.1@46.63,65.614 46.63,65.509 46.832,65.307 46.898,65.307 47.094,65.111 R18.2@47.094,64.397 47.102,64.389 47.102,63.404 R19.2@47.109,63.397 ; 33.934,68.758 34.934,67.758 35.128,67.564
BUZZER: IC1.31 Q3.1 | length 25.7
  Bottom Copper(SIG) w0.326: v1(17.28,60.722) IC1.31@17.28,62.404 17.28,60.927 19.329,58.877 27.33,58.877 30.124,56.083 30.124,54.712 32.503,52.333 v1(32.503,50.411) Q3.1@32.503,49.378
BYP: C26.1 U4.4 | length 1.6
  Bottom Copper(SIG) w0.326: C26.1@44.412,53.166 44.432,53.186 46.005,53.186 U4.4@46.025,53.206
CHARGE_STATUS: IC1.11 R9.1 R12.1 | length 69.8
  Top Copper (GND) w0.326: v1(22.758,86.589) 48.692,86.589 55.347,79.934 55.347,72.542 54.559,71.755 54.559,66.345 51.824,63.609 v1(51.824,57.108)
  Bottom Copper(SIG) w0.326: IC1.11@21.09,79.404 21.09,81.216 21.285,81.411 v1(21.285,81.431) 20.93,81.787 20.93,84.76 v1(22.758,86.589) ; v1(51.824,57.108) R12.1@52.895,57.108 52.922,57.081 53.819,57.081 R9.1@53.845,57.055
CMD_PYRO: C22.1 IC1.10 Q8.1 R28.2 | length 90.2
  Top Copper (GND) w0.326: v1(18.697,42.923) 15.065,46.555 15.065,60.318 16.789,62.042 16.789,84.171 17.911,85.293 18.694,85.293 19.785,84.203 v1(19.785,81.511)
  Bottom Copper(SIG) w0.326: v1(18.697,42.923) R28.2@25.277,42.923 ; v1(19.785,81.511) 19.785,81.491 19.82,81.456 IC1.10@19.82,79.404 ; C22.1@27.154,42.949 27.142,42.936 25.29,42.936 R28.2@25.277,42.923 ; Q8.1@44.361,31.616 45.734,31.616 v1@45.788,31.67 ; v1(45.808,31.67) v1@45.788,31.67 ; R28.2@25.277,42.923 25.244,42.957 23.881,42.957 v1(23.867,42.971) 27.235,42.971 34.9,35.306 37.291,35.306 40.927,31.67 v1@45.788,31.67
DETECT_CLIP: IC1.9 IC4.2 IC5.2 Q6.1 | length 87.9
  Top Copper (GND) w0.326: v1(18.572,81.633) 18.572,76.246 19.558,75.26 19.558,64.008 18.059,62.509 18.059,44.425 20.879,41.605 v1(20.879,34.696) ; v1(27.889,15.564) 28.455,14.998 28.848,14.998 29.399,14.447 29.399,13.906 31.864,13.906 32.107,13.663 v1(32.107,10.559)
  Bottom Copper(SIG) w0.326: IC1.9@18.55,79.404 18.561,79.415 18.561,81.621 v1(18.572,81.633) ; v1(20.879,34.696) 25.309,30.266 27.778,30.266 ; v1(27.889,15.564) 27.889,22.574 28.174,22.859 28.174,29.85 27.778,30.246 27.778,30.266 ; v1@27.913,15.588 27.913,15.574 27.923,15.565 29.144,15.565 29.281,15.701 IC5.2@29.281,16.026 ; Q6.1@29.353,30.266 27.778,30.266 ; IC4.2@31.044,10.524 31.079,10.559 v1(32.107,10.559)
DETECT_FIDLOCK: D9.6 IC1.7 U2.4 | length 68.9
  Top Copper (GND) w0.326: v1(34.724,51.532) 39.931,51.532 40.778,50.684 44.258,50.684 44.821,51.247 44.821,60.366 44.912,60.457 v1(44.912,69.012)
  Bottom Copper(SIG) w0.326: IC1.7@16.01,79.404 16.01,81.03 v1@16.245,81.265 ; v1(16.245,81.285) v1@16.245,81.265 ; v1(34.724,51.532) 34.724,51.512 34.882,51.354 34.882,50.976 34.921,50.936 D9.6@35.447,50.936 ; U2.4@44.973,70.59 44.949,70.59 44.912,70.553 v1(44.912,69.012) 37.16,69.012 32.708,73.464 32.708,73.867 32.222,74.354 31.818,74.354 28.118,78.054 16.739,78.054 16.245,78.548 v1@16.245,81.265
DETECT_PYRO_IN: C20.1 IC1.8 R26.2 R27.1 | length 42
  Top Copper (GND) w0.326: v1(17.221,52.603) 16.79,53.035 16.79,60.979 17.355,61.544 v1(17.355,81.591)
  Bottom Copper(SIG) w0.326: v1(17.221,52.603) 16.789,52.172 16.789,49.879 R26.2@17.377,49.879 17.377,47.889 18.15,47.116 19.688,47.116 R27.1@19.766,47.194 19.766,46.429 20.115,46.08 C20.1@21.06,46.08 ; IC1.8@17.28,79.404 17.28,81.496 17.355,81.571 v1(17.355,81.591)
DETECT_PYRO_OUT: IC1.30 Q5.1 | length 22.9
  Top Copper (GND) w0.326: v1(18.55,60.722) 18.55,50.571 21.742,47.379 v1(26.709,47.379)
  Bottom Copper(SIG) w0.326: v1(18.55,60.722) IC1.30@18.55,62.404 ; Q5.1@25.267,47.152 26.462,47.152 26.689,47.379 v1(26.709,47.379)
DETECT_SELLE: D7.1 IC1.26 IC7.3 R29.1 U2.6 | length 66.4
  Top Copper (GND) w0.326: v1(41.275,51.181) 41.678,51.584 v1(41.678,55.281) 40.875,56.083 40.875,57.662 v1(41.462,58.249) ; v1(41.904,62.378) 41.904,69.845 v1(44.899,72.84)
  Bottom Copper(SIG) w0.326: IC1.26@23.63,62.404 v1(23.63,60.404) 24.243,59.792 26.035,59.792 26.594,60.35 34.849,60.35 40.961,54.238 D7.1@41.699,54.238 41.688,54.248 41.688,55.27 v1(41.678,55.281) ; v1(41.275,51.181) 41.885,50.571 41.885,38.034 R29.1@40.687,36.837 41.609,36.837 41.884,37.113 v1(41.904,37.113) 41.908,37.109 41.908,36.059 IC7.3@41.912,36.055 ; v1(41.462,58.249) 41.904,58.691 v1(41.904,62.378) ; v1(44.899,72.84) 44.899,72.82 44.973,72.746 U2.6@44.973,71.89
DETECT_USB: IC1.12 IC8.8 R30.2 | length 64.8
  Top Copper (GND) w0.326: v1(22.587,81.531) 26.161,77.957 26.161,74.43 28.678,71.913 28.678,68.569 26.823,66.714 v1(26.823,63.187)
  Bottom Copper(SIG) w0.326: IC1.12@22.36,79.404 22.36,81.285 22.587,81.511 v1(22.587,81.531) ; v1(26.823,63.187) 26.823,62.026 27.312,61.537 37.241,61.537 39.52,59.258 R30.2@39.52,56.683 39.525,56.688 39.525,57.555 v1(39.53,57.559) 39.812,57.277 50.571,57.277 52.222,55.626 52.222,53.823 52.73,53.823 53.358,53.195 53.358,48.233 v1(53.278,48.152) 53.263,48.138 53.089,48.138 52.777,47.827 IC8.8@52.777,47.765
EN: C1.1 IC1.3 J3.1 R1.1 | length 42
  Top Copper (GND) w0.326: v1(22.098,77.495) 22.098,65.572 25.761,61.909 26.94,61.909 27.956,62.925 30.619,62.925 v1(31.153,63.459)
  Bottom Copper(SIG) w0.326: R1.1@11.803,84.162 11.641,84 11.641,83.61 10.995,82.963 C1.1@10.995,82.004 10.963,81.972 10.963,79.437 IC1.3@10.93,79.404 10.93,78.054 11.489,77.495 v1(22.098,77.495) ; v1(31.153,63.459) 31.167,63.473 31.256,63.473 J3.1@31.864,64.081
FLG: IC9.3 R32.1 | length 4.9
  Bottom Copper(SIG) w0.326: IC9.3@45.989,45.127 45.989,46.085 46.581,46.677 46.831,46.677 47.246,47.092 47.246,48.364 47.381,48.499 R32.1@47.381,49.336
